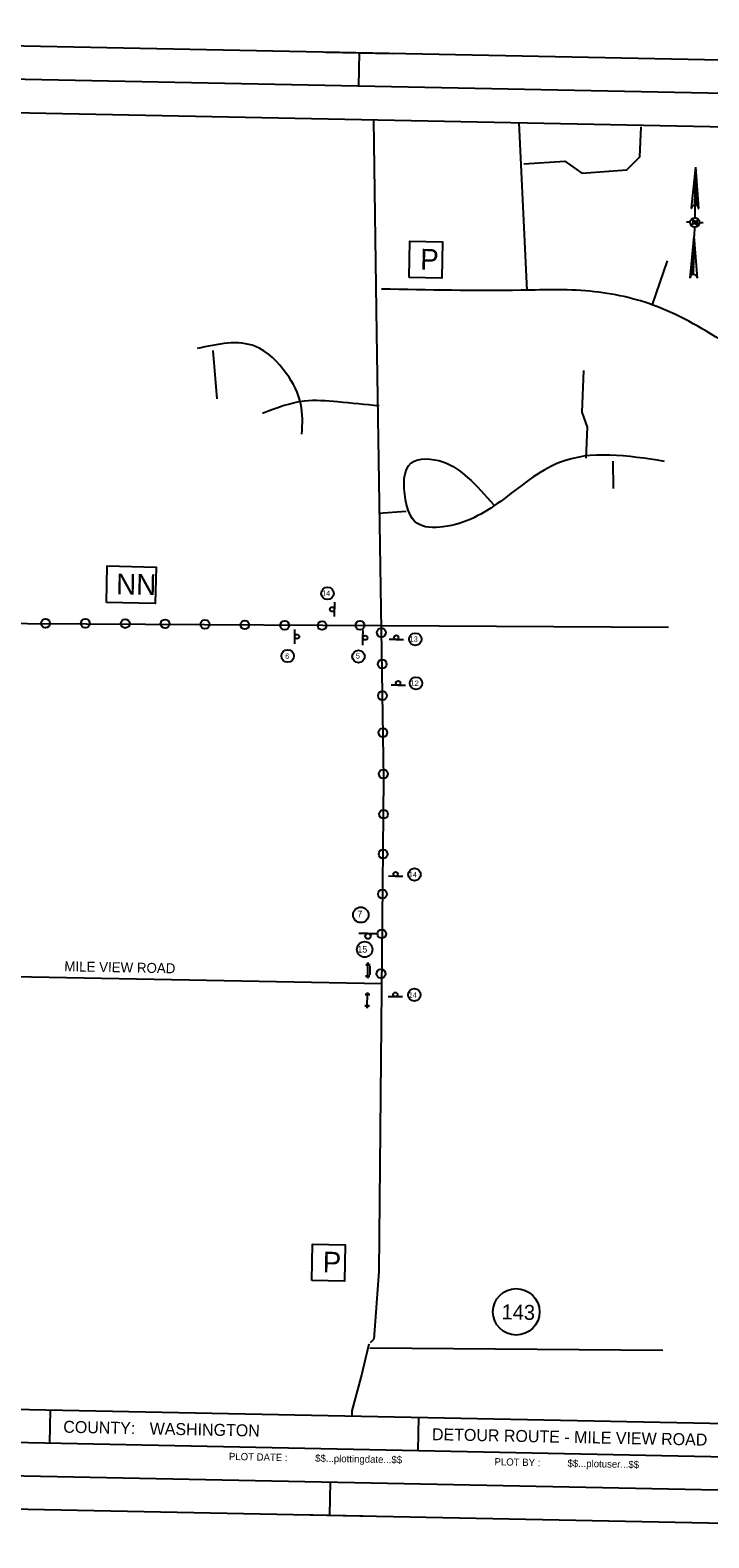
# Model space of a CAD drawing. Extents: x 299354 to 1325680, y 96128 to 228242.
# Drawn here: x 1314730 to 1319839, y 143563 to 154903 of the extents above; entities that cross this region are included whole.
import ezdxf

# ---------------------------------------------------------------- set-up
doc = ezdxf.new("R2010")
doc.units = 0
for name, color, linetype in [('CA-TBLK', 7, 'Continuous'), ('CA-TEXT', 7, 'Continuous'), ('CE-TOPO-CONC-SLAB', 7, 'Continuous'), ('Level 2', 7, 'Continuous'), ('Level 3', 7, 'Continuous'), ('Level 4', 7, 'Continuous'), ('P_TC', 7, 'Continuous'), ('PLT_Sheet_Border', 7, 'Continuous'), ('PLT_Sheet_Info', 7, 'Continuous'), ('SIGNS-POLES', 7, 'Continuous')]:
    doc.layers.add(name, color=color, linetype=linetype)

msp = doc.modelspace()

# ---------------------------------------------------------------- linework, layer by layer
at = {"layer": 'CA-TBLK'}
for p, q in [((1319709, 153564), (1319740, 153873)), ((1319734, 153588), (1319740, 153873)), ((1319738, 153808), (1319744, 153813)), ((1319744, 153813), (1319738, 153808)), ((1319743, 153808), (1319738, 153803)), ((1319738, 153798), (1319748, 153808)), ((1319748, 153803), (1319738, 153798)), ((1319738, 153793), (1319748, 153798)), ((1319748, 153798), (1319738, 153788)), ((1319748, 153793), (1319738, 153783)), ((1319738, 153788), (1319748, 153793)), ((1319738, 153778), (1319748, 153788)), ((1319738, 153773), (1319748, 153783)), ((1319748, 153783), (1319738, 153778)), ((1319748, 153778), (1319738, 153773)), ((1319738, 153768), (1319748, 153778)), ((1319748, 153773), (1319738, 153763)), ((1319745, 153858), (1319739, 153853)), ((1319739, 153853), (1319744, 153853)), ((1319739, 153843), (1319744, 153848)), ((1319744, 153848), (1319739, 153848)), ((1319739, 153838), (1319744, 153843)), ((1319744, 153843), (1319739, 153843)), ((1319744, 153838), (1319739, 153833)), ((1319744, 153833), (1319739, 153828)), ((1319739, 153833), (1319744, 153833)), ((1319744, 153828), (1319739, 153823)), ((1319739, 153828), (1319744, 153828)), ((1319744, 153823), (1319739, 153818)), ((1319739, 153818), (1319744, 153823)), ((1319739, 153813), (1319744, 153818)), ((1319764, 153562), (1319740, 153873)), ((1319740, 153873), (1319740, 153873)), ((1319740, 153873), (1319740, 153873)), ((1319740, 153868), (1319740, 153868)), ((1319740, 153863), (1319745, 153863)), ((1319745, 153863), (1319740, 153863)), ((1319740, 153858), (1319745, 153858)), ((1319735, 153658), (1319756, 153673)), ((1319756, 153673), (1319735, 153658)), ((1319735, 153648), (1319756, 153668)), ((1319756, 153668), (1319735, 153653)), ((1319756, 153663), (1319735, 153648)), ((1319736, 153708), (1319752, 153718)), ((1319752, 153718), (1319736, 153703)), ((1319752, 153713), (1319736, 153698)), ((1319736, 153703), (1319752, 153713)), ((1319736, 153693), (1319751, 153708)), ((1319736, 153688), (1319751, 153703)), ((1319751, 153703), (1319736, 153693)), ((1319736, 153683), (1319751, 153698)), ((1319751, 153698), (1319736, 153683)), ((1319751, 153693), (1319736, 153678)), ((1319751, 153688), (1319736, 153673)), ((1319736, 153673), (1319751, 153688)), ((1319756, 153683), (1319736, 153663)), ((1319736, 153668), (1319756, 153683)), ((1319736, 153663), (1319756, 153678)), ((1319737, 153758), (1319748, 153768)), ((1319737, 153753), (1319748, 153763)), ((1319748, 153763), (1319737, 153758)), ((1319747, 153758), (1319737, 153748)), ((1319737, 153748), (1319747, 153758)), ((1319747, 153753), (1319737, 153743)), ((1319747, 153748), (1319737, 153738)), ((1319737, 153738), (1319747, 153748)), ((1319752, 153743), (1319737, 153728)), ((1319737, 153733), (1319752, 153743)), ((1319737, 153728), (1319752, 153738)), ((1319737, 153718), (1319752, 153733)), ((1319752, 153733), (1319737, 153723)), ((1319737, 153713), (1319752, 153728)), ((1319752, 153728), (1319737, 153718)), ((1319752, 153723), (1319737, 153713)), ((1319734, 153588), (1319732, 153493)), ((1319755, 153628), (1319734, 153608)), ((1319734, 153608), (1319755, 153628)), ((1319760, 153622), (1319734, 153598)), ((1319734, 153603), (1319760, 153622)), ((1319734, 153598), (1319760, 153617)), ((1319734, 153593), (1319760, 153612)), ((1319760, 153612), (1319734, 153593)), ((1319759, 153608), (1319734, 153588)), ((1319755, 153658), (1319735, 153638)), ((1319735, 153643), (1319755, 153658)), ((1319755, 153653), (1319735, 153633)), ((1319735, 153638), (1319755, 153653)), ((1319735, 153628), (1319755, 153648)), ((1319735, 153623), (1319755, 153643)), ((1319755, 153643), (1319735, 153628)), ((1319735, 153618), (1319755, 153638)), ((1319755, 153638), (1319735, 153618)), ((1319755, 153633), (1319735, 153613)), ((1319739, 153588), (1319759, 153608)), ((1319759, 153603), (1319744, 153588)), ((1319744, 153588), (1319759, 153598)), ((1319759, 153598), (1319749, 153583)), ((1319759, 153593), (1319749, 153583)), ((1319749, 153583), (1319759, 153593)), ((1319754, 153583), (1319759, 153588)), ((1319759, 153583), (1319754, 153578)), ((1319754, 153578), (1319759, 153583)), ((1319759, 153573), (1319759, 153578)), ((1319759, 153578), (1319759, 153578)), ((1319759, 153573), (1319759, 153573)), ((1319759, 153568), (1319759, 153568)), ((1319759, 153568), (1319759, 153568)), ((1319759, 153563), (1319764, 153562)), ((1319696, 153459), (1319671, 153459)), ((1319717, 153473), (1319716, 153438)), ((1319716, 153458), (1319732, 153468)), ((1319727, 153468), (1319716, 153458)), ((1319716, 153458), (1319727, 153468)), ((1319716, 153458), (1319751, 153438)), ((1319727, 153473), (1319717, 153463)), ((1319717, 153468), (1319722, 153473)), ((1319722, 153473), (1319717, 153468)), ((1319717, 153473), (1319717, 153473)), ((1319751, 153458), (1319717, 153473)), ((1319732, 153468), (1319721, 153453)), ((1319721, 153453), (1319737, 153463)), ((1319726, 153453), (1319742, 153463)), ((1319737, 153463), (1319726, 153453)), ((1319731, 153448), (1319742, 153463)), ((1319742, 153463), (1319731, 153453)), ((1319751, 153458), (1319736, 153448)), ((1319736, 153448), (1319746, 153458)), ((1319746, 153458), (1319736, 153448)), ((1319741, 153443), (1319751, 153453)), ((1319751, 153453), (1319741, 153443)), ((1319746, 153443), (1319751, 153448)), ((1319751, 153448), (1319746, 153443)), ((1319752, 153473), (1319751, 153438)), ((1319751, 153438), (1319751, 153443)), ((1319766, 153457), (1319796, 153457)), ((1319698, 153039), (1319729, 153353)), ((1319724, 153068), (1319729, 153353)), ((1319731, 153423), (1319729, 153353)), ((1319753, 153038), (1319729, 153353)), ((1319729, 153353), (1319729, 153353)), ((1319729, 153348), (1319729, 153348)), ((1319729, 153348), (1319729, 153348)), ((1319729, 153343), (1319729, 153343)), ((1319729, 153338), (1319729, 153338)), ((1319729, 153338), (1319729, 153338)), ((1319729, 153333), (1319729, 153333)), ((1319729, 153328), (1319729, 153333)), ((1319729, 153328), (1319729, 153328)), ((1319729, 153323), (1319729, 153323)), ((1319729, 153323), (1319729, 153318)), ((1319729, 153318), (1319729, 153313)), ((1319729, 153318), (1319729, 153318)), ((1319716, 153208), (1319726, 153198)), ((1319717, 153238), (1319727, 153228)), ((1319717, 153233), (1319727, 153223)), ((1319727, 153228), (1319717, 153233)), ((1319717, 153228), (1319727, 153218)), ((1319727, 153218), (1319717, 153228)), ((1319727, 153213), (1319717, 153223)), ((1319726, 153208), (1319717, 153218)), ((1319717, 153218), (1319726, 153208)), ((1319726, 153198), (1319717, 153213)), ((1319717, 153213), (1319726, 153203)), ((1319722, 153258), (1319727, 153248)), ((1319727, 153253), (1319722, 153258)), ((1319722, 153253), (1319727, 153243)), ((1319727, 153243), (1319722, 153253)), ((1319727, 153238), (1319722, 153248)), ((1319727, 153233), (1319722, 153243)), ((1319722, 153243), (1319727, 153233)), ((1319723, 153298), (1319728, 153293)), ((1319728, 153293), (1319723, 153293)), ((1319723, 153293), (1319728, 153288)), ((1319723, 153288), (1319728, 153278)), ((1319728, 153283), (1319723, 153288)), ((1319728, 153278), (1319723, 153283)), ((1319728, 153273), (1319723, 153278)), ((1319723, 153278), (1319728, 153273)), ((1319728, 153263), (1319723, 153273)), ((1319723, 153273), (1319728, 153268)), ((1319723, 153268), (1319728, 153263)), ((1319723, 153263), (1319727, 153253)), ((1319727, 153258), (1319723, 153263)), ((1319728, 153308), (1319729, 153313)), ((1319728, 153303), (1319728, 153308)), ((1319728, 153308), (1319728, 153308)), ((1319728, 153303), (1319728, 153298)), ((1319728, 153298), (1319728, 153303)), ((1319704, 153109), (1319724, 153083)), ((1319724, 153088), (1319704, 153109)), ((1319724, 153083), (1319704, 153104)), ((1319724, 153078), (1319704, 153099)), ((1319704, 153099), (1319724, 153078)), ((1319724, 153068), (1319704, 153094)), ((1319704, 153094), (1319724, 153073)), ((1319705, 153114), (1319724, 153093)), ((1319724, 153093), (1319705, 153114)), ((1319710, 153158), (1319725, 153143)), ((1319725, 153143), (1319710, 153158)), ((1319725, 153133), (1319710, 153153)), ((1319710, 153153), (1319725, 153138)), ((1319710, 153148), (1319725, 153133)), ((1319710, 153143), (1319725, 153123)), ((1319725, 153128), (1319710, 153143)), ((1319710, 153138), (1319725, 153118)), ((1319725, 153123), (1319710, 153138)), ((1319725, 153113), (1319710, 153133)), ((1319724, 153108), (1319710, 153128)), ((1319710, 153128), (1319725, 153113)), ((1319724, 153103), (1319710, 153123)), ((1319710, 153123), (1319724, 153103)), ((1319710, 153118), (1319724, 153098)), ((1319726, 153168), (1319711, 153183)), ((1319711, 153178), (1319726, 153163)), ((1319711, 153173), (1319725, 153158)), ((1319725, 153158), (1319711, 153173)), ((1319711, 153168), (1319725, 153153)), ((1319725, 153153), (1319711, 153168)), ((1319725, 153148), (1319711, 153163)), ((1319716, 153203), (1319726, 153188)), ((1319726, 153193), (1319716, 153203)), ((1319726, 153188), (1319716, 153198)), ((1319716, 153198), (1319726, 153183)), ((1319726, 153178), (1319716, 153193)), ((1319726, 153173), (1319716, 153188)), ((1319716, 153188), (1319726, 153178)), ((1319716, 153183), (1319726, 153168)), ((1319698, 153059), (1319703, 153054)), ((1319698, 153054), (1319703, 153054)), ((1319703, 153054), (1319698, 153054)), ((1319698, 153049), (1319698, 153049)), ((1319698, 153049), (1319698, 153049)), ((1319698, 153044), (1319698, 153044)), ((1319703, 153059), (1319704, 153064)), ((1319704, 153089), (1319724, 153068)), ((1319704, 153084), (1319719, 153068)), ((1319724, 153068), (1319704, 153084)), ((1319704, 153079), (1319714, 153063)), ((1319719, 153063), (1319704, 153079)), ((1319714, 153063), (1319704, 153074)), ((1319708, 153058), (1319704, 153069)), ((1319704, 153069), (1319709, 153063)), ((1319704, 153064), (1319708, 153058))]:
    msp.add_line(p, q, dxfattribs=at)
msp.add_circle((1319733, 153457), 34.8, dxfattribs=at)
for centre, start, end in [((1319735, 153562), 358.8468, 178.8468), ((1319735, 153562), 178.8468243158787, 178.84682987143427), ((1319724, 153040), 358.8468, 178.8468), ((1319724, 153040), 358.84700764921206, 358.8470132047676)]:
    msp.add_arc(centre, 26.1, start, end, dxfattribs=at)
at = {"layer": 'CA-TEXT'}
for p, q in [((1317714, 153181), (1317714, 153181)), ((1315499, 150735), (1315499, 150735)), ((1316981, 145638), (1316981, 145638)), ((1318389, 145263), (1318389, 145263))]:
    msp.add_line(p, q, dxfattribs=at)
for points in [[(1317584, 153043), (1317589, 153316), (1317835, 153311), (1317829, 153038)], [(1315304, 150599), (1315310, 150873), (1315678, 150865), (1315672, 150591)], [(1316850, 145500), (1316856, 145773), (1317101, 145768), (1317096, 145495)]]:
    msp.add_lwpolyline(points, close=True, dxfattribs=at)
for centre, radius in [((1316968, 150667), 46.9), ((1317629, 150322), 46.9), ((1316669, 150196), 46.9), ((1317202, 150192), 46.9), ((1317634, 149991), 46.9), ((1317623, 148552), 46.9), ((1317219, 148249), 58.6), ((1317248, 147989), 58.6), ((1317622, 147647), 46.9), ((1318389, 145263), 175)]:
    msp.add_circle(centre, radius, dxfattribs=at)
at = {"layer": 'CE-TOPO-CONC-SLAB'}
for centre in [(1314846, 150442), (1315146, 150441), (1315446, 150440), (1315746, 150438), (1316046, 150434), (1316346, 150430), (1316646, 150426), (1316928, 150425), (1317213, 150426), (1317374, 150372), (1317380, 150135), (1317382, 149898), (1317385, 149620), (1317389, 149309), (1317390, 149006), (1317387, 148706), (1317382, 148406), (1317377, 148106), (1317371, 147806)]:
    msp.add_circle(centre, 33.5, dxfattribs=at)
at = {"layer": 'Level 2'}
for points in [[(1317153, 144481), (1317153, 144518), (1317222, 144768), (1317282, 145022)], [(1317286, 144993), (1319493, 144975)]]:
    msp.add_lwpolyline(points, dxfattribs=at)
at = {"layer": 'Level 3'}
for points in [[(1317315, 154229), (1317337, 152625), (1317389, 149275), (1317355, 145566), (1317317, 145058)], [(1312037, 150456), (1317378, 150425)], [(1317291, 145033), (1317317, 145058)]]:
    msp.add_lwpolyline(points, dxfattribs=at)
at = {"layer": 'Level 4'}
for p, q in [((1318471, 152946), (1318410, 154207)), ((1319415, 152840), (1319528, 153169)), ((1316106, 152493), (1316136, 152129)), ((1319115, 151661), (1319118, 151455)), ((1317353, 151271), (1317560, 151285))]:
    msp.add_line(p, q, dxfattribs=at)
for points in [[(1318446, 153899), (1318754, 153918), (1318883, 153828), (1319222, 153852), (1319318, 153951), (1319329, 154176)], [(1318915, 151684), (1318926, 151916), (1318885, 152029), (1318897, 152343)], [(1317378, 150425), (1319536, 150412)], [(1312030, 147815), (1314081, 147796), (1317375, 147733)]]:
    msp.add_lwpolyline(points, dxfattribs=at)
for points in [[(1320022, 152514), (1319477, 152813), (1318978, 152936), (1318427, 152947), (1317375, 152956)], [(1316776, 151865), (1316768, 152091), (1316660, 152319), (1316426, 152524), (1315987, 152508)], [(1316478, 152022), (1316794, 152115), (1317044, 152110), (1317357, 152079)], [(1319504, 151660), (1318714, 151651), (1318270, 151359), (1317840, 151167), (1317640, 151196), (1317556, 151373), (1317599, 151648), (1317837, 151656), (1318023, 151539), (1318219, 151335)]]:
    msp.add_spline(points, degree=3, dxfattribs=at)
at = {"layer": 'P_TC'}
for p, q in [((1317273, 147874), (1317273, 147891)), ((1317273, 147891), (1317273, 147874)), ((1317254, 147789), (1317271, 147789)), ((1317271, 147789), (1317254, 147789)), ((1317273, 147874), (1317256, 147874)), ((1317256, 147874), (1317273, 147874)), ((1317271, 147789), (1317273, 147874)), ((1317271, 147789), (1317271, 147772)), ((1317271, 147772), (1317271, 147789)), ((1317271, 147789), (1317288, 147788)), ((1317288, 147788), (1317271, 147789)), ((1317273, 147874), (1317290, 147873)), ((1317290, 147873), (1317273, 147874)), ((1317289, 147798), (1317290, 147863)), ((1317269, 147649), (1317252, 147649)), ((1317252, 147649), (1317269, 147649)), ((1317267, 147564), (1317269, 147649)), ((1317269, 147649), (1317269, 147666)), ((1317269, 147666), (1317269, 147649)), ((1317269, 147649), (1317286, 147649)), ((1317286, 147649), (1317269, 147649)), ((1317250, 147564), (1317267, 147564)), ((1317267, 147564), (1317250, 147564)), ((1317267, 147564), (1317267, 147547)), ((1317267, 147547), (1317267, 147564)), ((1317267, 147564), (1317284, 147564)), ((1317284, 147564), (1317267, 147564))]:
    msp.add_line(p, q, dxfattribs=at)
at = {"layer": 'PLT_Sheet_Border'}
for points in [[(1308462, 143905), (1325458, 143563), (1325680, 154561), (1308683, 154903)], [(1308587, 144153), (1325133, 143820), (1325345, 154318), (1308798, 154651)]]:
    msp.add_lwpolyline(points, close=True, dxfattribs=at)
at = {"layer": 'PLT_Sheet_Info'}
for p, q in [((1316956, 154737), (1317456, 154727)), ((1317206, 154732), (1317201, 154482)), ((1309305, 154391), (1325052, 154073)), ((1309109, 144643), (1324856, 144325)), ((1314878, 144276), (1314883, 144526)), ((1309104, 144393), (1324851, 144075)), ((1317652, 144220), (1317657, 144470)), ((1316985, 143734), (1316990, 143984)), ((1316735, 143739), (1317235, 143729))]:
    msp.add_line(p, q, dxfattribs=at)
at = {"layer": 'SIGNS-POLES'}
for p, q in [((1317020, 150601), (1317020, 150547)), ((1317019, 150547), (1317019, 150493)), ((1316723, 150342), (1316723, 150396)), ((1317235, 150333), (1317236, 150387)), ((1316722, 150287), (1316722, 150341)), ((1317235, 150278), (1317235, 150332)), ((1317486, 150319), (1317432, 150319)), ((1317540, 150318), (1317486, 150318)), ((1317501, 149976), (1317447, 149976)), ((1317555, 149975), (1317501, 149975)), ((1317481, 148538), (1317427, 148539)), ((1317536, 148537), (1317482, 148538)), ((1317205, 148110), (1317272, 148110)), ((1317273, 148109), (1317340, 148108)), ((1317480, 147632), (1317426, 147633)), ((1317534, 147632), (1317480, 147632))]:
    msp.add_line(p, q, dxfattribs=at)
for centre, radius in [((1317003, 150547), 16.7), ((1316739, 150342), 16.7), ((1317252, 150333), 16.7), ((1317486, 150335), 16.7), ((1317500, 149992), 16.7), ((1317481, 148555), 16.7), ((1317273, 148089), 20.9), ((1317479, 147649), 16.7)]:
    msp.add_circle(centre, radius, dxfattribs=at)

# ---------------------------------------------------------------- texts
at = {"layer": 'CA-TEXT'}
for s, height, rotation, p in [('P', 156, 358.767, (1317665, 153103)), ('NN', 156.2, 358.767, (1315376, 150660)), ('14', 40, 358.8468, (1316927, 150649)), ('13', 40, 358.8468, (1317586, 150304)), ('6', 40, 358.8468, (1316649, 150175)), ('5', 40, 358.8468, (1317181, 150177)), ('12', 40, 358.8468, (1317593, 149972)), ('14', 40, 358.8468, (1317580, 148533)), ('7', 50, 358.8468, (1317192, 148230)), ('15', 50, 358.8456, (1317193, 147966)), ('MILE VIEW ROAD', 75, 358.9016, (1314987, 147825)), ('14', 40, 358.8468, (1317579, 147627)), ('P', 156, 358.767, (1316931, 145560)), ('143', 112.5, 358.767, (1318278, 145207))]:
    msp.add_text(s, height=height, rotation=rotation, dxfattribs=at).set_placement(p)
at = {"layer": 'PLT_Sheet_Info'}
for s, height, p in [('COUNTY:', 90, (1314979, 144354)), ('WASHINGTON          ', 90, (1315629, 144341)), ('DETOUR ROUTE - MILE VIEW ROAD                        ', 90, (1317754, 144298)), ('PLOT DATE :', 54, (1316226, 144149)), ('$$...plottingdate...$$', 54, (1316875, 144136)), ('PLOT BY :', 54, (1318225, 144109)), ('$$...plotuser...$$', 54, (1318775, 144098))]:
    msp.add_text(s, height=height, rotation=358.8462, dxfattribs=at).set_placement(p)

doc.saveas('drawing.dxf')
